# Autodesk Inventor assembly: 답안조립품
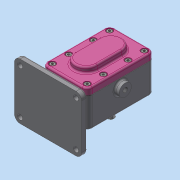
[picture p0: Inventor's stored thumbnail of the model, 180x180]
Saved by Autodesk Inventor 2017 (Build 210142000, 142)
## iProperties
Part Number: 답안조립품
Material: 일반
Document SubType Name: Assembly
Designer: MRC
Author: MRC
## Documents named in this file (11)
- C:\Users\MRC\Desktop\700407V1047\답안조립품.iam
- C:\Users\MRC\Desktop\700407V1047\본체.ipt
- C:\Users\MRC\Desktop\700407V1047\Ű 6 x 6 x 18.ipt
- C:\Users\MRC\Desktop\700407V1047\개스킷.ipt
- C:\Users\MRC\Desktop\700407V1047\메인축.ipt
- C:\Users\MRC\Desktop\700407V1047\베어링부시.ipt
- C:\Users\MRC\Desktop\700407V1047\볼트 M5.ipt
- C:\Users\MRC\Desktop\700407V1047\서브축.ipt
- C:\Users\MRC\Desktop\700407V1047\스퍼기어.ipt
- C:\Users\MRC\Desktop\700407V1047\오일 실 16 28 7.ipt
- C:\Users\MRC\Desktop\700407V1047\커버.ipt
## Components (3 placed, 2 different names)
1. Ű 6 x 6 x 18:1
2. 개스킷:1
3. Ű 6 x 6 x 18:2
